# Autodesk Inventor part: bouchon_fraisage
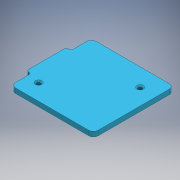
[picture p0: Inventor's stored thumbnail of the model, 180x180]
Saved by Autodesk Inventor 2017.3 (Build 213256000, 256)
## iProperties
Part Number: bouchon_fraisage
Material: Générique
Document SubType Name: Modeling
Designer: ficho
Density: 1 g/cm^3
Appearance: Turquoise
Author: ficho
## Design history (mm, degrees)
node "Plan de construction1"
sketch "Esquisse2"
  geometry: L1 (-40.15, -6)-(5, -6); L2 (8, -3)-(8, 40.9); L3 (5, 43.9)-(-40.15, 43.9); L4 (-43.161, 40.9)-(-43.15, -3); A1 r 3 centre (5, -3) between (5, -6) and (8, -3); A2 r 3 centre (5, 40.9) between (8, 40.9) and (5, 43.9); A3 r 3.011 centre (-40.15, 40.889) between (-40.15, 43.9) and (-43.161, 40.9); A4 r 3.001 centre (-40.149, -2.999) between (-43.15, -3) and (-40.15, -6); 1 further point
  constraints: 8 end point, 8 point on circle, 6 tangent, 4 centre point, 2 perpendicular, 1 horizontal, 8 other
extrude "Extrusion1" new body sketch "Esquisse2" distance "d6" = 3; taper "d7" = 0 deg
sketch "Esquisse4"
  geometry: L1 (36, 0)-(0, 0) reference; L2 (-3, 3)-(-3, 34.9) reference; L3 (0, 37.9)-(40.15, 37.9) reference; L4 (40.15, 0)-(36, 0) reference; L5 (40.15, 0)-(40.15, 37.9); A1 r 3 centre (0, 3) between (-3, 3) and (0, 0) reference; A2 r 3 centre (0, 34.9) between (0, 37.9) and (-3, 34.9) reference; 1 further point
  constraints: 2 end point, 1 vertical
extrude "Extrusion3" join sketch "Esquisse4" distance "d13" = 3; taper "d14" = 0 deg
sketch "Esquisse5"
  geometry: C1 r 0.755 at (-2, 32.9) reference; C2 r 0.755 at (-36, 4) reference; 1 further point
hole "Perçage1" sketch "Esquisse5" at (-2, 32.9), (-36, 4) diameter "d15" = 2.5; stored, may be unused: countersink angle "d19" = 90 deg, drill point angle "d21" = 118 deg; dims "d16" = 6, "d17" = 4, "d18" = 2, "d20" = 8
sketch "Esquisse6"
  geometry: C1 r 4 at (2, 32.9) reference; C2 r 4 at (36, 4) reference; 1 further point
extrude "Extrusion4" cut sketch "Esquisse6" distance "d22" = 3; taper "d23" = 0 deg
sketch "Esquisse7"
  geometry: L1 (-43.161, 6.601)-(-46.161, 6.601); L2 (-46.161, 6.601)-(-46.161, 31.299); L3 (-46.161, 31.299)-(-43.161, 31.299); L4 (-43.161, 31.299)-(-43.161, 6.601); A1 r 8 centre (-50, 2.45) between (-43.161, 6.601) and (-50, 10.45) reference; A2 r 8 centre (-50, 35.45) between (-50, 27.45) and (-43.161, 31.299) reference; 1 further point
  constraints: 8 end point, 2 parallel, 1 horizontal, 1 perpendicular
  dimensions: "d24" = 3 distance of L2.end L3.end
extrude "Extrusion5" join sketch "Esquisse7" distance "d25" = 5; taper "d26" = 0 deg
sketch "Esquisse8"
  geometry: L1 (10.6, 22.4)-(9.1, 22.4) reference; L2 (9.1, 21.337)-(3, 21.337); L3 (3, 31.9)-(3, 0) reference; L4 (9.1, 21.337)-(9.1, 22.4); L5 (10.6, 22.4)-(10.6, 21.9); L6 (10.6, 21.9)-(13.558, 22.4); L7 (13.558, 22.4)-(13.558, 23.275); L8 (13.558, 23.275)-(3, 23.275); L9 (3, 21.337)-(3, 23.275); L10 (10.6, 6.7)-(10.6, 22.4) reference; L11 (10.6, 14.55)-(6.256, 14.55); L12 (10.6, 6.7)-(9.1, 6.7); L13 (9.1, 7.763)-(3, 7.763); L14 (9.1, 7.763)-(9.1, 6.7); L15 (10.6, 6.7)-(10.6, 7.2); L16 (10.6, 7.2)-(13.558, 6.7); L17 (13.558, 6.7)-(13.558, 5.825); L18 (13.558, 5.825)-(3, 5.825); L19 (3, 7.763)-(3, 5.825); 1 further point
  constraints: 36 end point, 7 symmetric about line, 3 horizontal, 2 parallel, 2 perpendicular, 2 point on line, 1 collinear, 1 midpoint, 1 vertical, 3 other
  dimensions: "d28" = 0.5 distance of L1.start L5.end; "d29" = 3 distance of L5.end L6.end
extrude "Extrusion6" join sketch "Esquisse8" distance "d30" = 40; taper "d31" = 0 deg
sketch "Esquisse9"
  geometry: L1 (0, 0)-(-40, 0) reference; L2 (-33.239, 0)-(-13.239, 0); L3 (-13.239, 0)-(-13.239, 13.834); L4 (-13.239, 13.834)-(-33.239, 13.834); L5 (-33.239, 13.834)-(-33.239, 0); L6 (-5.738, 0)-(7.369, 0); L7 (7.369, 0)-(7.369, 13.834); L8 (7.369, 13.834)-(-5.738, 13.834); L9 (-5.738, 13.834)-(-5.738, 0); 1 further point
  constraints: 16 end point, 4 parallel, 3 point on line, 2 horizontal, 2 perpendicular
  dimensions: "d32" = 20 distance of L4.end L3.end; "d33" = 7.50046 distance between parallel lines of L9 L3
extrude "Extrusion7" cut sketch "Esquisse9" stored distance "d34" = 40; taper "d35" = 0 deg
sketch "Esquisse10"
  geometry: L1 (-3, -3)-(-3, 5) reference; L2 (-3, -3)-(-21.802, -3); L3 (-21.802, -3)-(-21.802, 60.017); L4 (-21.802, 60.017)-(-3, 60.017); L5 (-3, 60.017)-(-3, -3); 1 further point
  constraints: 8 end point, 2 parallel, 1 horizontal, 1 perpendicular
extrude "Extrusion8" cut sketch "Esquisse10" stored distance "d36" = 0; taper "d37" = 0 deg
sketch "Esquisse11"
  geometry: L1 (3, -3)-(3, 0) reference; L2 (3.012, -3)-(3, -3); L3 (3, -3)-(3, 0); L4 (3, 0)-(3.012, 0); L5 (3.012, 0)-(3.012, -3); 1 further point
  constraints: 8 end point, 2 parallel, 1 horizontal, 1 perpendicular
extrude "Extrusion9" join sketch "Esquisse11" stored distance "d38" = 10; taper "d39" = 0 deg
fillet "Congé4" dims "d40" = 1.5
sketch "Esquisse12"
  geometry: L1 (44.661, 31.299)-(44.659, 31.299); L2 (44.652, 6.601)-(44.661, 6.601); L3 (43.161, 32.721)-(43.16, 29.8); L4 (43.161, 8.101)-(43.161, 5.264); A1 r 1.5 centre (44.652, 5.101) between (44.652, 6.601) and (43.161, 5.264); A2 r 1.5 centre (44.661, 8.101) between (43.161, 8.101) and (44.661, 6.601); A3 r 1.5 centre (44.66, 29.799) between (44.661, 31.299) and (43.16, 29.8); A4 r 1.5 centre (44.659, 32.799) between (43.161, 32.721) and (44.659, 31.299) reference; 2 further points
  constraints: 6 point on circle, 4 end point, 3 centre point, 1 point on line
extrude "Extrusion12" cut sketch "Esquisse12" distance "d45" = 2; taper "d46" = 0 deg
extrude "Extrusion13" cut sketch "Esquisse12" distance "d47" = 2; taper "d48" = 0 deg
node "Solide1"
node "Référence16"
node "Référence17"
node "Référence18"
node "Référence19"
node "Référence20"
node "Référence21"
node "Référence22"
node "Référence23"
node "Référence24"
node "Référence26"
node "Référence27"
node "Référence28"
